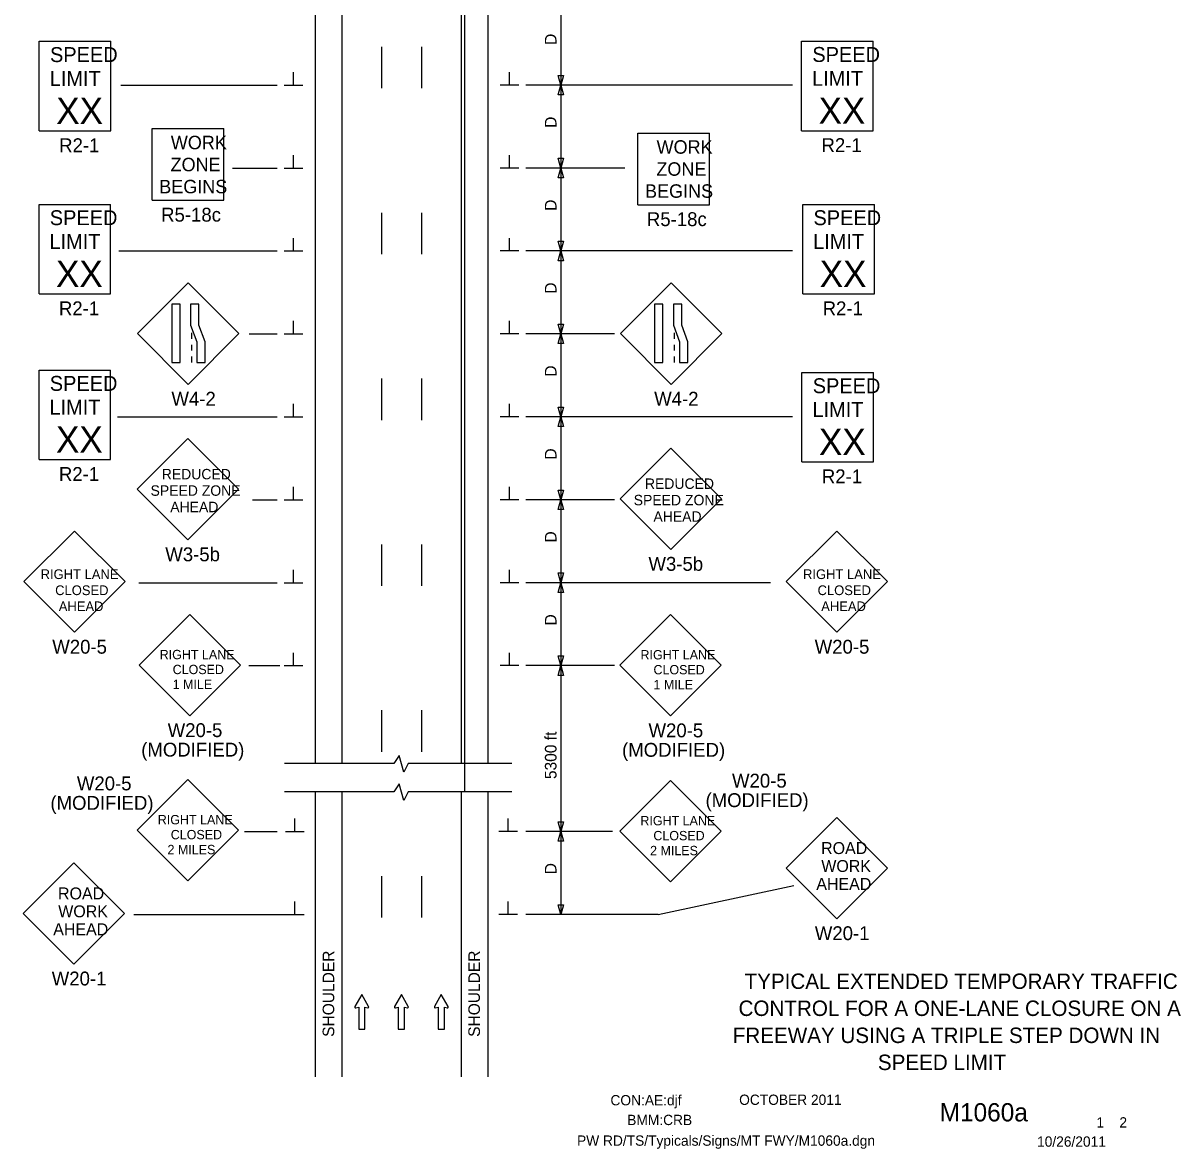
# Model space of a CAD drawing. Extents: x 16737 to 18479, y 5932 to 6964.
# Drawn here: x 16737 to 17435, y 5932 to 6610 of the extents above; entities that cross this region are included whole.
import ezdxf

# ---------------------------------------------------------------- set-up
doc = ezdxf.new("R2010")
doc.units = 0
for name, color, linetype in [('ALI_LEGAL_EX', 7, 'Continuous'), ('BORDER', 7, 'Continuous'), ('BORDER_SIGNAL_WO', 7, 'Continuous'), ('MT_SCRATCH_LEVEL_E', 7, 'Continuous'), ('PAVT_EDGE_EX', 7, 'Continuous'), ('TRAFFIC_SIGNS_PR', 7, 'Continuous'), ('TYPICAL_TEXT_DIMEN_PR', 7, 'Continuous')]:
    doc.layers.add(name, color=color, linetype=linetype)

msp = doc.modelspace()

# ---------------------------------------------------------------- linework, layer by layer
at = {"layer": 'ALI_LEGAL_EX'}
msp.add_line((17002.72, 6964.07), (17002.72, 6147.1), dxfattribs=at)
for points in [[(16952.72, 6596.22), (16952.72, 6571.22)], [(16976.72, 6596.22), (16976.72, 6571.22)], [(16952.72, 6496.22), (16952.72, 6471.22)], [(16976.72, 6496.22), (16976.72, 6471.22)], [(16952.72, 6396.22), (16952.72, 6371.22)], [(16976.72, 6396.22), (16976.72, 6371.22)], [(16952.72, 6296.22), (16952.72, 6271.22)], [(16976.72, 6296.22), (16976.72, 6271.22)], [(16952.72, 6196.22), (16952.72, 6171.22)], [(16976.72, 6196.22), (16976.72, 6171.22)], [(16952.72, 6096.22), (16952.72, 6071.22)], [(16976.72, 6096.22), (16976.72, 6071.22)]]:
    msp.add_lwpolyline(points, dxfattribs=at)
at = {"layer": 'MT_SCRATCH_LEVEL_E'}
for p, q in [((16940.72, 6024.82), (16936.61, 6017.57)), ((16944.87, 6017.57), (16940.72, 6024.82)), ((16964.62, 6024.82), (16960.51, 6017.57)), ((16968.77, 6017.57), (16964.62, 6024.82)), ((16988.68, 6024.82), (16984.56, 6017.57)), ((16992.82, 6017.57), (16988.68, 6024.82)), ((16937.09, 6016.89), (16938.87, 6017.21)), ((16938.87, 6017.21), (16938.87, 6003.95)), ((16942.61, 6003.95), (16942.61, 6017.21)), ((16942.61, 6017.21), (16944.39, 6016.89)), ((16960.99, 6016.89), (16962.77, 6017.21)), ((16962.77, 6017.21), (16962.77, 6003.95)), ((16966.51, 6003.95), (16966.51, 6017.21)), ((16966.51, 6017.21), (16968.29, 6016.89)), ((16985.05, 6016.89), (16986.82, 6017.21)), ((16986.82, 6017.21), (16986.82, 6003.95)), ((16990.57, 6003.95), (16990.57, 6017.21)), ((16990.57, 6017.21), (16992.34, 6016.89)), ((16938.87, 6003.95), (16942.61, 6003.95)), ((16962.77, 6003.95), (16966.51, 6003.95)), ((16986.82, 6003.95), (16990.57, 6003.95))]:
    msp.add_line(p, q, dxfattribs=at)
for centre, start, end in [((16937.02, 6017.35), 150.42484, 279.96381), ((16944.46, 6017.35), 260.03619, 29.77312), ((16960.92, 6017.35), 150.42484, 279.96381), ((16968.36, 6017.35), 260.03619, 29.77312), ((16984.97, 6017.35), 150.42484, 279.96381), ((16992.41, 6017.35), 260.03619, 29.77312)]:
    msp.add_arc(centre, 0.463, start, end, dxfattribs=at)
at = {"layer": 'PAVT_EDGE_EX'}
for p, q in [((16912.72, 6926.76), (16912.72, 6164.15)), ((16928.72, 6926.76), (16928.72, 6164.15)), ((17000.72, 6926.76), (17000.72, 6164.15)), ((17016.72, 6926.76), (17016.72, 6164.15)), ((16912.72, 6147.02), (16912.72, 5975.18)), ((16928.72, 6147.02), (16928.72, 5975.18)), ((17000.72, 6147.02), (17000.72, 5975.18)), ((17016.72, 6147.02), (17016.72, 5975.18))]:
    msp.add_line(p, q, dxfattribs=at)
at = {"layer": 'TRAFFIC_SIGNS_PR'}
for p, q in [((16746.27, 6599.56), (16789.47, 6599.56)), ((16746.27, 6545.56), (16746.27, 6599.56)), ((16789.47, 6545.56), (16789.47, 6599.56)), ((17205.94, 6599.64), (17249.14, 6599.64)), ((17205.94, 6545.64), (17205.94, 6599.64)), ((17249.14, 6545.64), (17249.14, 6599.64)), ((16746.27, 6545.56), (16789.47, 6545.56)), ((16814.34, 6503.68), (16814.34, 6546.88)), ((16814.34, 6546.88), (16857.54, 6546.88)), ((16857.54, 6503.68), (16857.54, 6546.88)), ((17107.26, 6500.99), (17107.26, 6544.19)), ((17107.26, 6544.19), (17150.46, 6544.19)), ((17150.46, 6500.99), (17150.46, 6544.19)), ((17205.94, 6545.64), (17249.14, 6545.64)), ((16746.12, 6501.23), (16789.32, 6501.23)), ((16746.12, 6447.23), (16746.12, 6501.23)), ((16789.32, 6447.23), (16789.32, 6501.23)), ((16814.34, 6503.68), (16857.54, 6503.68)), ((17107.26, 6500.99), (17150.46, 6500.99)), ((17206.62, 6501.23), (17249.82, 6501.23)), ((17206.62, 6447.23), (17206.62, 6501.23)), ((17249.82, 6447.23), (17249.82, 6501.23)), ((16836.14, 6453.84), (16805.59, 6423.29)), ((16866.69, 6423.29), (16836.14, 6453.84)), ((17127.23, 6453.84), (17096.68, 6423.29)), ((17157.78, 6423.29), (17127.23, 6453.84)), ((16746.12, 6447.23), (16789.32, 6447.23)), ((17206.62, 6447.23), (17249.82, 6447.23)), ((16805.59, 6423.29), (16836.14, 6392.74)), ((16836.14, 6392.74), (16866.69, 6423.29)), ((16837.98, 6423.84), (16837.98, 6420.24)), ((17096.68, 6423.29), (17127.23, 6392.74)), ((17127.23, 6392.74), (17157.78, 6423.29)), ((17129.07, 6423.84), (17129.07, 6420.24)), ((16837.98, 6416.64), (16837.98, 6413.04)), ((17129.07, 6416.64), (17129.07, 6413.04)), ((16837.98, 6409.44), (16837.98, 6405.84)), ((17129.07, 6409.44), (17129.07, 6405.84)), ((16746.12, 6401.35), (16789.32, 6401.35)), ((16746.12, 6347.35), (16746.12, 6401.35)), ((16789.32, 6347.35), (16789.32, 6401.35)), ((17206.16, 6399.93), (17249.36, 6399.93)), ((17206.16, 6345.93), (17206.16, 6399.93)), ((17249.36, 6345.93), (17249.36, 6399.93)), ((16835.82, 6360.03), (16805.27, 6329.48)), ((16866.37, 6329.48), (16835.82, 6360.03)), ((17127.17, 6354.28), (17096.62, 6323.73)), ((17157.71, 6323.73), (17127.17, 6354.28)), ((16746.12, 6347.35), (16789.32, 6347.35)), ((17206.16, 6345.93), (17249.36, 6345.93)), ((16805.27, 6329.48), (16835.82, 6298.94)), ((16835.82, 6298.94), (16866.37, 6329.48)), ((17096.62, 6323.73), (17127.17, 6293.19)), ((17127.17, 6293.19), (17157.71, 6323.73)), ((16767.43, 6304.32), (16736.88, 6273.78)), ((16797.98, 6273.78), (16767.43, 6304.32)), ((17227.15, 6304.32), (17196.6, 6273.78)), ((17257.7, 6273.78), (17227.15, 6304.32)), ((16736.88, 6273.78), (16767.43, 6243.23)), ((16767.43, 6243.23), (16797.98, 6273.78)), ((17196.6, 6273.78), (17227.15, 6243.23)), ((17227.15, 6243.23), (17257.7, 6273.78)), ((16837.02, 6254.03), (16806.47, 6223.48)), ((16867.56, 6223.48), (16837.02, 6254.03)), ((17126.95, 6253.9), (17096.4, 6223.35)), ((17157.49, 6223.35), (17126.95, 6253.9)), ((16806.47, 6223.48), (16837.02, 6192.93)), ((16837.02, 6192.93), (16867.56, 6223.48)), ((17096.4, 6223.35), (17126.95, 6192.8)), ((17126.95, 6192.8), (17157.49, 6223.35)), ((16835.88, 6154.47), (16805.34, 6123.92)), ((16866.43, 6123.92), (16835.88, 6154.47)), ((17126.87, 6153.87), (17096.32, 6123.33)), ((17157.42, 6123.33), (17126.87, 6153.87)), ((17227.22, 6131.62), (17196.68, 6101.07)), ((17257.77, 6101.07), (17227.22, 6131.62)), ((16805.34, 6123.92), (16835.88, 6093.37)), ((16835.88, 6093.37), (16866.43, 6123.92)), ((17096.32, 6123.33), (17126.87, 6092.78)), ((17126.87, 6092.78), (17157.42, 6123.33)), ((16767.11, 6104.29), (16736.56, 6073.75)), ((16797.66, 6073.75), (16767.11, 6104.29)), ((17196.68, 6101.07), (17227.22, 6070.52)), ((17227.22, 6070.52), (17257.77, 6101.07)), ((16736.56, 6073.75), (16767.11, 6043.2)), ((16767.11, 6043.2), (16797.66, 6073.75))]:
    msp.add_line(p, q, dxfattribs=at)
for points in [[(16826.13, 6440.99), (16826.13, 6405.84), (16831.19, 6405.84), (16831.19, 6440.99)], [(16837.53, 6440.99), (16837.53, 6428.41), (16841.3, 6418.42), (16841.3, 6405.84), (16846.35, 6405.84), (16846.35, 6418.42), (16842.59, 6428.41), (16842.59, 6440.99)], [(17117.22, 6440.99), (17117.22, 6405.84), (17122.28, 6405.84), (17122.28, 6440.99)], [(17128.62, 6440.99), (17128.62, 6428.41), (17132.39, 6418.42), (17132.39, 6405.84), (17137.44, 6405.84), (17137.44, 6418.42), (17133.68, 6428.41), (17133.68, 6440.99)]]:
    msp.add_lwpolyline(points, close=True, dxfattribs=at)
at = {"layer": 'TYPICAL_TEXT_DIMEN_PR'}
for p, q in [((17060.72, 6623.15), (17060.72, 6573.15)), ((16899.6, 6573.15), (16899.6, 6580.93)), ((17029.85, 6573.15), (17029.85, 6580.93)), ((17060.72, 6573.15), (17059.15, 6579.01)), ((17059.15, 6579.01), (17060.72, 6579.01)), ((17060.72, 6579.01), (17062.29, 6579.01)), ((17062.29, 6579.01), (17060.72, 6573.15)), ((16795.49, 6573.15), (16889.72, 6573.15)), ((16893.97, 6573.15), (16905.22, 6573.15)), ((17035.47, 6573.15), (17024.22, 6573.15)), ((17200.56, 6573.15), (17039.72, 6573.15)), ((17059.15, 6567.29), (17060.72, 6573.15)), ((17060.72, 6573.15), (17060.72, 6523.15)), ((17060.72, 6573.15), (17062.29, 6567.29)), ((17060.72, 6567.29), (17059.15, 6567.29)), ((17062.29, 6567.29), (17060.72, 6567.29)), ((16899.6, 6523.15), (16899.6, 6530.93)), ((17029.85, 6523.15), (17029.85, 6530.93)), ((17060.72, 6523.15), (17059.15, 6529.01)), ((17059.15, 6529.01), (17060.72, 6529.01)), ((17060.72, 6529.01), (17062.29, 6529.01)), ((17062.29, 6529.01), (17060.72, 6523.15)), ((16862.83, 6523.15), (16889.72, 6523.15)), ((16893.97, 6523.15), (16905.22, 6523.15)), ((17035.47, 6523.15), (17024.22, 6523.15)), ((17099.44, 6523.15), (17039.72, 6523.15)), ((17059.15, 6517.29), (17060.72, 6523.15)), ((17060.72, 6523.15), (17060.72, 6473.15)), ((17060.72, 6523.15), (17062.29, 6517.29)), ((17060.72, 6517.29), (17059.15, 6517.29)), ((17062.29, 6517.29), (17060.72, 6517.29)), ((16899.6, 6473.15), (16899.6, 6480.93)), ((17029.85, 6473.15), (17029.85, 6480.93)), ((17060.72, 6473.15), (17059.15, 6479.01)), ((17059.15, 6479.01), (17060.72, 6479.01)), ((17060.72, 6479.01), (17062.29, 6479.01)), ((17062.29, 6479.01), (17060.72, 6473.15)), ((16794.27, 6473.15), (16889.72, 6473.15)), ((16893.97, 6473.15), (16905.22, 6473.15)), ((17035.47, 6473.15), (17024.22, 6473.15)), ((17200.56, 6473.15), (17039.72, 6473.15)), ((17059.15, 6467.29), (17060.72, 6473.15)), ((17060.72, 6473.15), (17060.72, 6423.15)), ((17060.72, 6473.15), (17062.29, 6467.29)), ((17060.72, 6467.29), (17059.15, 6467.29)), ((17062.29, 6467.29), (17060.72, 6467.29)), ((16899.6, 6423.15), (16899.6, 6430.93)), ((17029.85, 6423.15), (17029.85, 6430.93)), ((16872.75, 6423.15), (16889.72, 6423.15)), ((16893.97, 6423.15), (16905.22, 6423.15)), ((17035.47, 6423.15), (17024.22, 6423.15)), ((17093.08, 6423.15), (17039.72, 6423.15)), ((17060.72, 6423.15), (17059.15, 6429.01)), ((17059.15, 6429.01), (17060.72, 6429.01)), ((17059.15, 6417.29), (17060.72, 6423.15)), ((17060.72, 6429.01), (17062.29, 6429.01)), ((17062.29, 6429.01), (17060.72, 6423.15)), ((17060.72, 6423.15), (17060.72, 6373.15)), ((17060.72, 6423.15), (17062.29, 6417.29)), ((17060.72, 6417.29), (17059.15, 6417.29)), ((17062.29, 6417.29), (17060.72, 6417.29)), ((16899.6, 6373.15), (16899.6, 6380.93)), ((17029.85, 6373.15), (17029.85, 6380.93)), ((17060.72, 6373.15), (17059.15, 6379.01)), ((17059.15, 6379.01), (17060.72, 6379.01)), ((17060.72, 6379.01), (17062.29, 6379.01)), ((17062.29, 6379.01), (17060.72, 6373.15)), ((16793.45, 6373.15), (16889.72, 6373.15)), ((16893.97, 6373.15), (16905.22, 6373.15)), ((17035.47, 6373.15), (17024.22, 6373.15)), ((17200.56, 6373.15), (17039.72, 6373.15)), ((17059.15, 6367.29), (17060.72, 6373.15)), ((17060.72, 6367.29), (17059.15, 6367.29)), ((17060.72, 6373.15), (17060.72, 6323.15)), ((17060.72, 6373.15), (17062.29, 6367.29)), ((17062.29, 6367.29), (17060.72, 6367.29)), ((16899.6, 6323.15), (16899.6, 6330.93)), ((17029.85, 6323.15), (17029.85, 6330.93)), ((17060.72, 6323.15), (17059.15, 6329.01)), ((17059.15, 6329.01), (17060.72, 6329.01)), ((17060.72, 6329.01), (17062.29, 6329.01)), ((17062.29, 6329.01), (17060.72, 6323.15)), ((16874.94, 6323.15), (16889.72, 6323.15)), ((16893.97, 6323.15), (16905.22, 6323.15)), ((17035.47, 6323.15), (17024.22, 6323.15)), ((17093.08, 6323.15), (17039.72, 6323.15)), ((17059.15, 6317.29), (17060.72, 6323.15)), ((17060.72, 6323.15), (17060.72, 6273.15)), ((17060.72, 6323.15), (17062.29, 6317.29)), ((17060.72, 6317.29), (17059.15, 6317.29)), ((17062.29, 6317.29), (17060.72, 6317.29)), ((16899.6, 6273.15), (16899.6, 6280.93)), ((17029.85, 6273.15), (17029.85, 6280.93)), ((17060.72, 6273.15), (17059.15, 6279.01)), ((17059.15, 6279.01), (17060.72, 6279.01)), ((17060.72, 6279.01), (17062.29, 6279.01)), ((17062.29, 6279.01), (17060.72, 6273.15)), ((16806.24, 6273.15), (16889.72, 6273.15)), ((16893.97, 6273.15), (16905.22, 6273.15)), ((17035.47, 6273.15), (17024.22, 6273.15)), ((17187.21, 6273.15), (17039.72, 6273.15)), ((17059.15, 6267.29), (17060.72, 6273.15)), ((17060.72, 6273.15), (17060.72, 6223.15)), ((17060.72, 6273.15), (17062.29, 6267.29)), ((17060.72, 6267.29), (17059.15, 6267.29)), ((17062.29, 6267.29), (17060.72, 6267.29)), ((16899.6, 6223.15), (16899.6, 6230.93)), ((17029.85, 6223.15), (17029.85, 6230.93)), ((17060.72, 6223.15), (17059.15, 6229.01)), ((17059.15, 6229.01), (17060.72, 6229.01)), ((17060.72, 6229.01), (17062.29, 6229.01)), ((17062.29, 6229.01), (17060.72, 6223.15)), ((16872.55, 6223.15), (16891.37, 6223.15)), ((16893.97, 6223.15), (16905.22, 6223.15)), ((17035.47, 6223.15), (17024.22, 6223.15)), ((17093.08, 6223.15), (17039.72, 6223.15)), ((17075.05, 6223.15), (17039.72, 6223.15)), ((17059.15, 6217.29), (17060.72, 6223.15)), ((17060.72, 6223.15), (17060.72, 6123.15)), ((17060.72, 6223.15), (17062.29, 6217.29)), ((17060.72, 6217.29), (17059.15, 6217.29)), ((17062.29, 6217.29), (17060.72, 6217.29)), ((16960.07, 6164.15), (16894.13, 6164.15)), ((16963.32, 6168.95), (16960.07, 6164.15)), ((16966.07, 6159.02), (16963.32, 6168.95)), ((16968.81, 6164.15), (16966.07, 6159.02)), ((17031.14, 6164.15), (16968.81, 6164.15)), ((16963.32, 6151.82), (16960.07, 6147.02)), ((16966.07, 6141.88), (16963.32, 6151.82)), ((16960.07, 6147.02), (16894.13, 6147.02)), ((16968.81, 6147.02), (16966.07, 6141.88)), ((17031.14, 6147.02), (16968.81, 6147.02)), ((16900.35, 6123.15), (16900.35, 6130.93)), ((17029.1, 6123.15), (17029.1, 6130.93)), ((17060.72, 6123.15), (17059.15, 6129.01)), ((17059.15, 6129.01), (17060.72, 6129.01)), ((17060.72, 6129.01), (17062.29, 6129.01)), ((17062.29, 6129.01), (17060.72, 6123.15)), ((16870.05, 6123.15), (16889.72, 6123.15)), ((16894.72, 6123.15), (16905.97, 6123.15)), ((17034.72, 6123.15), (17023.47, 6123.15)), ((17092, 6123.15), (17039.72, 6123.15)), ((17059.15, 6117.29), (17060.72, 6123.15)), ((17060.72, 6123.15), (17060.72, 6073.15)), ((17060.72, 6123.15), (17062.29, 6117.29)), ((17060.72, 6117.29), (17059.15, 6117.29)), ((17062.29, 6117.29), (17060.72, 6117.29)), ((17119.45, 6073.15), (17201.24, 6090.53)), ((16900.35, 6073.15), (16900.35, 6080.93)), ((17029.1, 6073.15), (17029.1, 6080.93)), ((16803.3, 6073.15), (16902.72, 6073.15)), ((16894.72, 6073.15), (16905.97, 6073.15)), ((17034.72, 6073.15), (17023.47, 6073.15)), ((17119.45, 6073.15), (17039.72, 6073.15)), ((17060.72, 6073.15), (17059.15, 6079.01)), ((17059.15, 6079.01), (17060.72, 6079.01)), ((17060.72, 6079.01), (17062.29, 6079.01)), ((17062.29, 6079.01), (17060.72, 6073.15))]:
    msp.add_line(p, q, dxfattribs=at)

# ---------------------------------------------------------------- texts
at = {"layer": 'BORDER'}
for s, p in [('TYPICAL EXTENDED TEMPORARY TRAFFIC', (17171.54, 6028.24)), ('CONTROL FOR A ONE-LANE CLOSURE ON A', (17167.92, 6011.94)), ('FREEWAY USING A TRIPLE STEP DOWN IN ', (17164.42, 5995.64)), ('SPEED LIMIT', (17251.92, 5979.34))]:
    msp.add_text(s, height=9.3, dxfattribs=at).set_placement(p)
at = {"layer": 'BORDER_SIGNAL_WO'}
for s, height, p in [('CON:AE:djf  ', 6.2, (17090.69, 5958.06)), ('    OCTOBER 2011    ', 6.2, (17159.08, 5958.34)), ('    M1060a   ', 11, (17272.86, 5948.38)), ('BMM:CRB   ', 6.2, (17100.81, 5946.17)), (' 1    2 ', 6.2, (17381.45, 5944.7)), ('PW RD/TS/Typicals/Signs/MT FWY/M1060a.dgn      ', 6.2, (17070.55, 5933.71)), ('10/26/2011    ', 6.2, (17347.93, 5933.13))]:
    msp.add_text(s, height=height, dxfattribs=at).set_placement(p)
at = {"layer": 'TRAFFIC_SIGNS_PR'}
for s, height, p in [('SPEED', 9, (16752.76, 6587.02)), ('SPEED', 9, (17212.42, 6587.1)), ('LIMIT', 9, (16752.58, 6572.62)), ('LIMIT', 9, (17212.24, 6572.7)), ('XX', 15.785, (16756.52, 6549.78)), ('XX', 15.785, (17216.19, 6549.86)), ('R2-1', 8.37, (16758.28, 6532.69)), ('WORK', 8.119, (16825.6, 6534.47)), ('R2-1', 8.37, (17217.95, 6532.77)), ('WORK', 8.119, (17118.51, 6531.77)), ('ZONE', 8.119, (16825.46, 6521.19)), ('ZONE', 8.119, (17118.37, 6518.49)), ('BEGINS', 8.119, (16818.63, 6507.9)), ('BEGINS', 8.119, (17111.54, 6505.2)), ('R5-18c', 8.37, (16819.76, 6490.82)), ('SPEED', 9, (16752.61, 6488.7)), ('R5-18c', 8.37, (17112.67, 6488.12)), ('SPEED', 9, (17213.11, 6488.7)), ('LIMIT', 9, (16752.43, 6474.3)), ('LIMIT', 9, (17212.93, 6474.3)), ('XX', 15.785, (16756.37, 6451.46)), ('XX', 15.785, (17216.88, 6451.46)), ('R2-1', 8.37, (16758.13, 6434.36)), ('R2-1', 8.37, (17218.64, 6434.36)), ('SPEED', 9, (16752.61, 6388.82)), ('SPEED', 9, (17212.65, 6387.4)), ('W4-2', 8.37, (16825.97, 6379.87)), ('W4-2', 8.37, (17117.06, 6379.87)), ('LIMIT', 9, (16752.43, 6374.42)), ('LIMIT', 9, (17212.47, 6373)), ('XX', 15.785, (16756.37, 6351.58)), ('XX', 15.785, (17216.42, 6350.16)), ('R2-1', 8.37, (16758.13, 6334.48)), ('REDUCED', 6.3, (16820.13, 6335.45)), ('R2-1', 8.37, (17218.17, 6333.06)), ('SPEED ZONE', 6.3, (16813.37, 6325.55)), ('REDUCED', 6.3, (17111.48, 6329.7)), ('SPEED ZONE', 6.3, (17104.72, 6319.81)), ('AHEAD', 6.3, (16825.26, 6315.65)), ('AHEAD', 6.3, (17116.6, 6309.9)), ('W3-5b', 8.37, (16822.27, 6286.07)), ('W3-5b', 8.37, (17113.61, 6280.32)), ('RIGHT LANE', 5.85, (16747.09, 6275.35)), ('RIGHT LANE', 5.85, (17206.81, 6275.35)), ('CLOSED', 5.85, (16755.86, 6265.67)), ('CLOSED', 5.85, (17215.58, 6265.67)), ('AHEAD', 5.85, (16758.04, 6256)), ('AHEAD', 5.85, (17217.77, 6256)), ('W20-5', 8.37, (16754.12, 6230.36)), ('W20-5', 8.37, (17213.84, 6230.36)), ('RIGHT LANE', 5.625, (16818.88, 6227.03)), ('RIGHT LANE', 5.625, (17108.81, 6226.9)), ('CLOSED', 5.625, (16826.71, 6218.03)), ('CLOSED', 5.625, (17116.64, 6217.9)), ('1 MILE', 5.625, (16826.7, 6209.03)), ('1 MILE', 5.625, (17116.63, 6208.9)), ('W20-5', 8.37, (16823.71, 6180.07)), ('W20-5', 8.37, (17113.64, 6179.93)), ('(MODIFIED)', 8.37, (16807.76, 6168.32)), ('(MODIFIED)', 8.37, (17097.69, 6168.19)), ('W20-5', 8.37, (17163.99, 6149.61)), ('W20-5', 8.37, (16768.95, 6147.97)), ('(MODIFIED)', 8.37, (16753, 6136.22)), ('(MODIFIED)', 8.37, (17148.03, 6137.86)), ('RIGHT LANE', 5.625, (16817.75, 6127.47)), ('RIGHT LANE', 5.625, (17108.73, 6126.87)), ('CLOSED', 5.625, (16825.57, 6118.47)), ('CLOSED', 5.625, (17116.56, 6117.87)), ('2 MILES', 5.625, (16823.61, 6109.47)), ('ROAD', 7.2, (17217.71, 6109.55)), ('2 MILES', 5.625, (17114.59, 6108.87)), ('WORK', 7.2, (17217.83, 6098.75)), ('AHEAD', 7.2, (17214.81, 6087.95)), ('ROAD', 7.2, (16757.59, 6082.22)), ('WORK', 7.2, (16757.72, 6071.42)), ('AHEAD', 7.2, (16754.69, 6060.62)), ('W20-1', 8.37, (17213.92, 6057.65)), ('W20-1', 8.37, (16753.8, 6030.33))]:
    msp.add_text(s, height=height, dxfattribs=at).set_placement(p)
at = {"layer": 'TYPICAL_TEXT_DIMEN_PR'}
for s, p in [('D', (17058.16, 6597.37)), ('D', (17058.16, 6547.37)), ('D', (17058.16, 6497.37)), ('D', (17058.16, 6447.37)), ('D', (17058.16, 6397.37)), ('D', (17058.16, 6347.37)), ('D', (17058.16, 6297.37)), ('D', (17058.16, 6247.37)), ('5300 ft', (17058.16, 6154.75)), ('D', (17058.16, 6097.37)), ('SHOULDER', (16924.14, 5999.36)), ('SHOULDER', (17012, 5999.36))]:
    msp.add_text(s, height=7, rotation=90, dxfattribs=at).set_placement(p)

doc.saveas('drawing.dxf')
